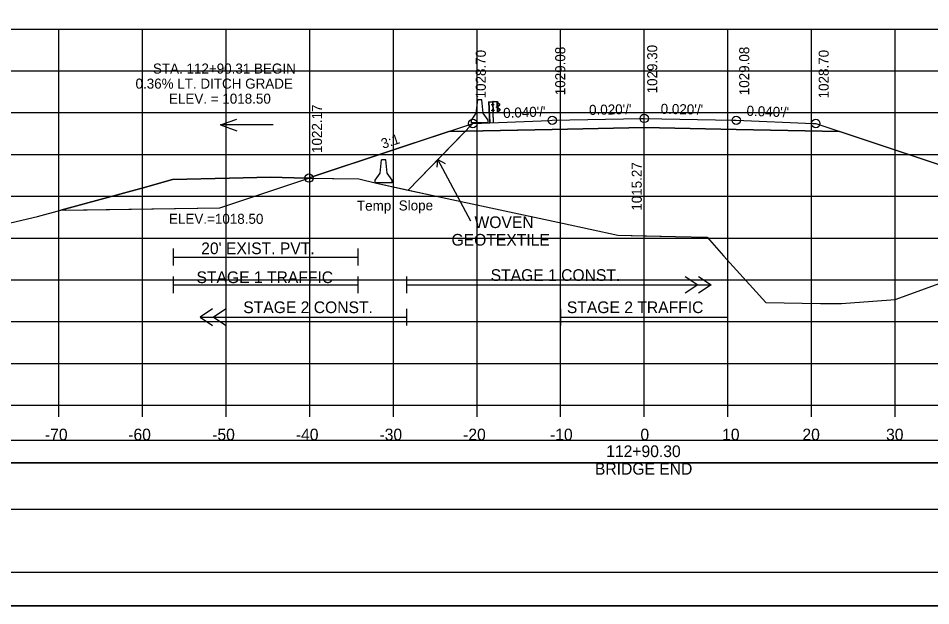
# Model space of a CAD drawing. Extents: x 1370565 to 1374448, y 301010 to 304637.
# Drawn here: x 1370660.2 to 1370769.3, y 302503.9 to 302574.1 of the extents above; entities that cross this region are included whole.
import ezdxf

# ---------------------------------------------------------------- set-up
doc = ezdxf.new("R2010")
doc.units = 0
for name, color, linetype in [('Default', 7, 'Continuous'), ('R_Alt Surface', 7, 'Continuous'), ('R_Axis', 7, 'Continuous'), ('R_Axis Annot', 7, 'Continuous'), ('R_Border', 7, 'Continuous'), ('R_Contours', 7, 'Continuous'), ('R_Drive', 7, 'Continuous'), ('R_Exist Surface', 7, 'Continuous'), ('R_Fin Surface', 7, 'Continuous'), ('R_Grid', 7, 'Continuous'), ('R_MOT', 7, 'Continuous'), ('R_No Plot', 7, 'Continuous'), ('R_Proposed Road', 7, 'Continuous'), ('R_Water', 7, 'Continuous'), ('R_Water Annot', 7, 'Continuous'), ('R_Xsect Elev', 7, 'Continuous'), ('R_Xsect Slope', 7, 'Continuous')]:
    doc.layers.add(name, color=color, linetype=linetype)

# ---------------------------------------------------------------- blocks, each defined once
blk = doc.blocks.new('GUARDRAIL LT_P')
at = {"layer": 'R_Proposed Road'}
for p, q in [((0, 2.52), (0, 0)), ((0.03, 2.52), (0.03, 0)), ((0.4, 2.11), (0.4, 2.2)), ((0.46, 2.21), (0.41, 2.21)), ((0.46, 2.18), (0.41, 2.18)), ((0.53, 2.52), (0.46, 2.51)), ((0.46, 2.09), (0.46, 2.21)), ((0.49, 0), (0.49, 2.52)), ((0.53, 2.52), (0.52, 2.52)), ((0.53, 2.21), (0.58, 2.21)), ((0.58, 2.21), (0.58, 2.08)), ((1.02, 1.15), (1.02, 2.51)), ((1.17, 2.3), (1.06, 2.36)), ((1.16, 2.29), (1.06, 2.34)), ((1.28, 2.18), (1.16, 2.29)), ((1.3, 2.2), (1.17, 2.3)), ((0.39, 1.42), (0.39, 1.51)), ((0.45, 1.53), (0.4, 1.53)), ((0.45, 1.49), (0.4, 1.49)), ((0.45, 1.43), (0.4, 1.43)), ((0.45, 1.43), (0.4, 1.43)), ((0.45, 1.4), (0.4, 1.4)), ((0.46, 2.12), (0.41, 2.12)), ((0.46, 2.12), (0.41, 2.12)), ((0.46, 2.09), (0.41, 2.09)), ((0.45, 1.4), (0.45, 1.53)), ((0.52, 1.15), (0.49, 1.15)), ((0.58, 2.15), (0.52, 2.15)), ((0.58, 1.46), (0.52, 1.46)), ((0.53, 2.08), (0.58, 2.08)), ((0.58, 1.53), (0.53, 1.53)), ((0.58, 1.4), (0.53, 1.4)), ((0.58, 1.4), (0.58, 1.53)), ((1.01, 1.89), (0.96, 1.89)), ((0.96, 1.78), (0.96, 1.88)), ((1.01, 1.86), (0.96, 1.86)), ((1.01, 1.8), (0.96, 1.8)), ((1.01, 1.77), (0.96, 1.77)), ((1.01, 1.8), (0.97, 1.8)), ((1.01, 1.77), (1.01, 1.89)), ((1.05, 1.31), (1.16, 1.37)), ((1.06, 1.77), (1.06, 1.9)), ((1.06, 1.29), (1.17, 1.35)), ((1.09, 1.77), (1.09, 1.9)), ((1.26, 1.6), (1.1, 1.69)), ((1.11, 1.97), (1.28, 2.07)), ((1.12, 1.95), (1.29, 2.05)), ((1.27, 1.62), (1.12, 1.71)), ((1.16, 1.37), (1.29, 1.48)), ((1.17, 1.35), (1.3, 1.46))]:
    blk.add_line(p, q, dxfattribs=at)
blk.add_lwpolyline([(0, 2.52), (0.46, 2.51), (0.45, 0)], dxfattribs=at)
for points in [[(0.4, 2.18), (0.4, 2.12), (0.37, 2.12), (0.37, 2.18)], [(0.45, 2.23), (0.45, 2.07), (0.46, 2.07), (0.46, 2.23)], [(1.05, 2.52), (1.05, 1.15), (0.52, 1.15), (0.53, 2.52)], [(0.58, 2.21), (0.58, 2.08), (0.53, 2.08), (0.53, 2.21)], [(0.39, 1.49), (0.39, 1.43), (0.36, 1.43), (0.36, 1.49)], [(0.44, 1.55), (0.44, 1.38), (0.45, 1.38), (0.45, 1.55)], [(0.58, 1.53), (0.58, 1.4), (0.53, 1.4), (0.53, 1.53)], [(0.95, 1.86), (0.95, 1.8), (0.93, 1.8), (0.93, 1.86)], [(1.01, 1.91), (1.01, 1.75), (1.02, 1.75), (1.02, 1.91)]]:
    blk.add_lwpolyline(points, close=True, dxfattribs=at)
for centre, radius, start, end in [((0.42, 2.2), 0.022, 134.5745, 222.2244), ((0.49, 2.15), 0.0922, 159.7423, 200.2577), ((1.25, 2.13), 0.0856, 299.2499, 57.9783), ((0.41, 1.51), 0.022, 134.5745, 222.2244), ((0.48, 1.46), 0.0922, 159.7423, 200.2577), ((0.41, 1.41), 0.025, 140.9334, 216.6234), ((0.43, 2.1), 0.025, 140.9334, 216.6234), ((0.98, 1.88), 0.022, 134.5745, 222.2244), ((1.05, 1.83), 0.0922, 159.7423, 200.2577), ((0.98, 1.78), 0.025, 140.9334, 216.6234), ((1.15, 1.89), 0.0865, 118.106, 175.0444), ((1.13, 1.76), 0.0703, 171.7804, 246.8536), ((1.08, 1.83), 0.0453, 282.9554, 86.0697), ((1.15, 1.89), 0.0622, 118.106, 175.0444), ((1.13, 1.76), 0.0462, 171.7804, 246.8536), ((1.22, 1.52), 0.0854, 325.2184, 59.12), ((1.22, 1.52), 0.109, 325.2184, 59.12), ((1.25, 2.13), 0.062, 299.2499, 57.9783)]:
    blk.add_arc(centre, radius, start, end, dxfattribs=at)
blk = doc.blocks.new('MEDBAR_P')
at = {"layer": 'R_MOT'}
for p, q in [((-2.46, -0.98), (-1.63, 6.93)), ((-0.38, 6.93), (-1.63, 6.93)), ((0.87, 6.93), (-0.38, 6.93)), ((1.71, -0.98), (0.87, 6.93)), ((-5.37, -6.81), (-5.34, -5.15)), ((-5.34, -5.15), (-2.46, -0.98)), ((4.66, -5.15), (1.71, -0.98)), ((4.63, -6.81), (4.66, -5.15)), ((4.63, -6.81), (-5.37, -6.81))]:
    blk.add_line(p, q, dxfattribs=at)

msp = doc.modelspace()

# ---------------------------------------------------------------- linework, layer by layer
at = {"layer": 'R_Alt Surface'}
for points in [[(1370711.67, 302560.59), (1370724.03, 302560.84), (1370735.03, 302561.06), (1370746.03, 302560.84), (1370758.38, 302560.59)], [(1370710.27, 302556.3), (1370710.36, 302557.24), (1370711.24, 302556.76)], [(1370714.28, 302549.85), (1370710.36, 302557.24)], [(1370706.61, 302543.24), (1370706.61, 302541.24)], [(1370739.92, 302543.24), (1370741.42, 302542.24), (1370739.92, 302541.24)], [(1370741.52, 302543.24), (1370743.02, 302542.24), (1370741.52, 302541.24)], [(1370706.61, 302542.24), (1370743.02, 302542.24)], [(1370683.42, 302539.38), (1370681.92, 302538.38), (1370683.42, 302537.38)], [(1370685.02, 302539.38), (1370683.52, 302538.38), (1370685.02, 302537.38)], [(1370706.61, 302539.38), (1370706.61, 302537.38)], [(1370725.03, 302539.38), (1370725.03, 302537.38)], [(1370681.92, 302538.38), (1370706.61, 302538.38)], [(1370725.03, 302538.38), (1370745.03, 302538.38)]]:
    msp.add_lwpolyline(points, dxfattribs=at)
at = {"layer": 'R_Axis'}
for p, q in [((1370585.03, 302527.84), (1370885.03, 302527.84)), ((1370665.03, 302526.44), (1370665.03, 302527.84)), ((1370675.03, 302526.44), (1370675.03, 302527.84)), ((1370685.03, 302526.44), (1370685.03, 302527.84)), ((1370695.03, 302526.44), (1370695.03, 302527.84)), ((1370705.03, 302526.44), (1370705.03, 302527.84)), ((1370715.03, 302526.44), (1370715.03, 302527.84)), ((1370725.03, 302526.44), (1370725.03, 302527.84)), ((1370735.03, 302526.44), (1370735.03, 302527.84)), ((1370745.03, 302526.44), (1370745.03, 302527.84)), ((1370755.03, 302526.44), (1370755.03, 302527.84)), ((1370765.03, 302526.44), (1370765.03, 302527.84))]:
    msp.add_line(p, q, dxfattribs=at)
for points in [[(1370678.71, 302546.57), (1370678.71, 302544.57)], [(1370700.78, 302546.57), (1370700.78, 302544.57)], [(1370678.71, 302545.57), (1370700.78, 302545.57)], [(1370678.71, 302543.24), (1370678.71, 302541.24)], [(1370700.78, 302543.24), (1370700.78, 302541.24)], [(1370678.71, 302542.24), (1370700.78, 302542.24)]]:
    msp.add_lwpolyline(points, dxfattribs=at)
at = {"layer": 'R_Border'}
msp.add_line((1370893.21, 302507.84), (1370577.03, 302507.84), dxfattribs=at)
at = {"layer": 'R_Contours'}
for p, q in [((1370713.64, 302560.63), (1370706.81, 302553.58)), ((1370706.81, 302553.58), (1370713.64, 302560.63)), ((1370713.64, 302560.63), (1370711.67, 302560.59)), ((1370694.94, 302555.01), (1370694.57, 302555.02))]:
    msp.add_line(p, q, dxfattribs=at)
for points in [[(1370711.67, 302560.59), (1370695.57, 302555.22), (1370694.94, 302555.01)], [(1370758.38, 302560.59), (1370746.03, 302560.84), (1370735.03, 302561.06), (1370724.03, 302560.84), (1370713.64, 302560.63)], [(1370796.27, 302547.96), (1370794.96, 302548.4), (1370758.38, 302560.59)], [(1370694.57, 302555.02), (1370690.35, 302555.11), (1370685.44, 302554.99), (1370678.61, 302554.86), (1370675.11, 302553.85), (1370665.25, 302551.17)], [(1370665.25, 302551.17), (1370684.28, 302551.46), (1370694.94, 302555.01)], [(1370694.94, 302555.01), (1370700.88, 302554.91), (1370703, 302554.4), (1370706.81, 302553.58)], [(1370706.81, 302553.58), (1370709.79, 302552.94), (1370725.24, 302549.62), (1370731.85, 302548.2), (1370735.03, 302548.11), (1370738.78, 302548.01), (1370742.56, 302547.94), (1370744.49, 302545.7), (1370749.55, 302540.13), (1370756.11, 302540.02), (1370758.61, 302540.02), (1370764.51, 302540.46), (1370765.02, 302540.5), (1370773.47, 302543.56), (1370780.96, 302546.27), (1370781.94, 302546.68), (1370796.27, 302547.96)]]:
    msp.add_lwpolyline(points, dxfattribs=at)
at = {"layer": 'R_Drive'}
for points in [[(1370585.82, 302520.94), (1370884.24, 302520.94), (1370884.24, 302523.64), (1370585.82, 302523.64)], [(1370585.82, 302515.41), (1370884.24, 302515.41), (1370884.24, 302520.94), (1370585.82, 302520.94)]]:
    msp.add_lwpolyline(points, close=True, dxfattribs=at)
at = {"layer": 'R_Exist Surface'}
msp.add_lwpolyline([(1370658.59, 302549.49), (1370662.48, 302550.42), (1370675.11, 302553.85), (1370678.61, 302554.86), (1370685.44, 302554.99), (1370690.35, 302555.11), (1370694.57, 302555.02), (1370700.88, 302554.91), (1370703, 302554.4), (1370709.79, 302552.94), (1370725.24, 302549.62), (1370731.85, 302548.2), (1370738.78, 302548.01), (1370742.56, 302547.94), (1370744.49, 302545.7), (1370749.55, 302540.13), (1370756.11, 302540.02), (1370758.61, 302540.02), (1370764.51, 302540.46), (1370765.02, 302540.5), (1370773.47, 302543.56)], dxfattribs=at)
at = {"layer": 'R_Fin Surface'}
msp.add_line((1370714.53, 302561.54), (1370706.81, 302553.58), dxfattribs=at)
msp.add_lwpolyline([(1370665.78, 302551.18), (1370684.28, 302551.46), (1370694.94, 302555.01), (1370695.57, 302555.22), (1370714.53, 302561.54), (1370723.72, 302561.91), (1370724.03, 302561.92), (1370734.67, 302562.13), (1370735.03, 302562.14), (1370745.67, 302561.93), (1370746.03, 302561.92), (1370755.22, 302561.55), (1370755.53, 302561.54), (1370794.96, 302548.4), (1370796.27, 302547.96), (1370817.92, 302540.74), (1370818.64, 302540.5), (1370830.25, 302540.5), (1370830.64, 302540.5), (1370858.39, 302549.75), (1370859.31, 302550.06)], dxfattribs=at)
at = {"layer": 'R_Grid'}
for p, q in [((1370585.03, 302572.84), (1370885.03, 302572.84)), ((1370665.03, 302527.84), (1370665.03, 302572.84)), ((1370675.03, 302527.84), (1370675.03, 302572.84)), ((1370685.03, 302527.84), (1370685.03, 302572.84)), ((1370695.03, 302527.84), (1370695.03, 302572.84)), ((1370705.03, 302527.84), (1370705.03, 302572.84)), ((1370715.03, 302527.84), (1370715.03, 302572.84)), ((1370725.03, 302527.84), (1370725.03, 302572.84)), ((1370735.03, 302527.84), (1370735.03, 302572.84)), ((1370745.03, 302527.84), (1370745.03, 302572.84)), ((1370755.03, 302527.84), (1370755.03, 302572.84)), ((1370765.03, 302527.84), (1370765.03, 302572.84)), ((1370585.03, 302567.84), (1370885.03, 302567.84)), ((1370585.03, 302562.84), (1370885.03, 302562.84)), ((1370585.03, 302557.84), (1370885.03, 302557.84)), ((1370585.03, 302552.84), (1370885.03, 302552.84)), ((1370585.03, 302547.84), (1370885.03, 302547.84)), ((1370585.03, 302542.84), (1370885.03, 302542.84)), ((1370585.03, 302537.84), (1370885.03, 302537.84)), ((1370585.03, 302532.84), (1370885.03, 302532.84)), ((1370585.03, 302527.84), (1370885.03, 302527.84))]:
    msp.add_line(p, q, dxfattribs=at)
at = {"layer": 'R_No Plot'}
msp.add_line((1370564.63, 302503.86), (1370897.96, 302503.86), dxfattribs=at)
for points in [[(1370564.62, 302717.2), (1370897.96, 302717.2), (1370897.96, 302503.86), (1370564.62, 302503.86)], [(1370810.95, 302713.3), (1370830.57, 302713.3), (1370830.57, 302703.42), (1370846.68, 302703.42), (1370869.88, 302703.42), (1370869.88, 302670.75), (1370893.09, 302670.75), (1370893.21, 302507.84), (1370577.03, 302507.84), (1370577.03, 302713.3)]]:
    msp.add_lwpolyline(points, close=True, dxfattribs=at)
for centre in [(1370735.03, 302562.14), (1370714.53, 302561.54), (1370714.53, 302561.54), (1370724.03, 302561.92), (1370746.03, 302561.92), (1370755.53, 302561.54), (1370755.53, 302561.54), (1370694.94, 302555.01)]:
    msp.add_circle(centre, 0.5, dxfattribs=at)
at = {"layer": 'R_Water Annot'}
for p, q in [((1370684.37, 302561.36), (1370686.3, 302562.06)), ((1370690.66, 302561.36), (1370684.37, 302561.36)), ((1370684.37, 302561.36), (1370686.3, 302560.66))]:
    msp.add_line(p, q, dxfattribs=at)
at = {"layer": 'R_Xsect Elev'}
msp.add_line((1370735.03, 302548.11), (1370735.03, 302558.11), dxfattribs=at)

# ---------------------------------------------------------------- block references
at = {"layer": 'Default', "rotation": 2.322183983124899}
msp.add_blockref('GUARDRAIL LT_P', (1370716.52, 302561.62), dxfattribs=at)
at = {"layer": 'R_Fin Surface', "xscale": 0.2, "yscale": 0.20000000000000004}
for p in [(1370715.44, 302562.98), (1370703.94, 302555.8)]:
    msp.add_blockref('MEDBAR_P', p, dxfattribs=at)

# ---------------------------------------------------------------- texts
at = {"layer": 'R_Axis Annot'}
for s, p in [('WOVEN ', (1370714.73, 302549.03)), ('GEOTEXTILE', (1370711.98, 302546.93)), ("20' EXIST. PVT.", (1370682.05, 302545.91)), ('-70', (1370663.37, 302523.64)), ('-60', (1370673.33, 302523.64)), ('-50', (1370683.37, 302523.64)), ('-40', (1370693.37, 302523.64)), ('-30', (1370703.37, 302523.64)), ('-20', (1370713.37, 302523.64)), ('-10', (1370723.76, 302523.64)), ('0', (1370734.57, 302523.64)), ('10', (1370744.34, 302523.64)), ('20', (1370753.94, 302523.64)), ('30', (1370763.94, 302523.64)), ('112+90.30', (1370730.48, 302521.64)), ('BRIDGE END', (1370729.13, 302519.54))]:
    msp.add_text(s, height=1.4, dxfattribs=at).set_placement(p)
at = {"layer": 'R_Water'}
for s, p in [('STAGE 1 CONST.', (1370716.66, 302542.71)), ('STAGE 1 TRAFFIC', (1370681.49, 302542.45)), ('STAGE 2 CONST.', (1370687.08, 302538.86)), ('STAGE 2 TRAFFIC', (1370725.77, 302538.86))]:
    msp.add_text(s, height=1.4, dxfattribs=at).set_placement(p)
at = {"layer": 'R_Xsect Elev'}
for s, p in [('1028.70', (1370716.08, 302564.54)), ('1029.08', (1370725.58, 302564.92)), ('1029.30', (1370736.58, 302565.14)), ('1029.08', (1370747.58, 302564.92)), ('1028.70', (1370757.08, 302564.54)), ('1022.17', (1370696.49, 302558.01)), ('1015.27', (1370734.73, 302551.11))]:
    msp.add_text(s, height=1.2, rotation=90, dxfattribs=at).set_placement(p)
for s, p in [('STA. 112+90.31 BEGIN ', (1370676.28, 302567.51)), ('0.36% LT. DITCH GRADE', (1370674.2, 302565.71)), ('ELEV. = 1018.50', (1370678.2, 302563.91)), ('ELEV.=1018.50', (1370678.2, 302549.54))]:
    msp.add_text(s, height=1.2, dxfattribs=at).set_placement(p)
at = {"layer": 'R_Xsect Slope'}
for s, rotation, p in [("0.040'/'", 2.2906, (1370718.18, 302562.19)), ("0.020'/'", 1.1458, (1370728.44, 302562.56)), ("0.020'/'", 358.8542, (1370736.98, 302562.7)), ("0.040'/'", 357.7094, (1370747.24, 302562.47)), ('3:1', 18.4349, (1370703.79, 302558.49)), ('Temp. Slope', 0.3453, (1370700.68, 302551.1))]:
    msp.add_text(s, height=1.2, rotation=rotation, dxfattribs=at).set_placement(p)

doc.saveas('drawing.dxf')
